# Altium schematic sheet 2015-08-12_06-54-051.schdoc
size 557 x 193 mm; SheetNumber: 1; SheetTotal: 1
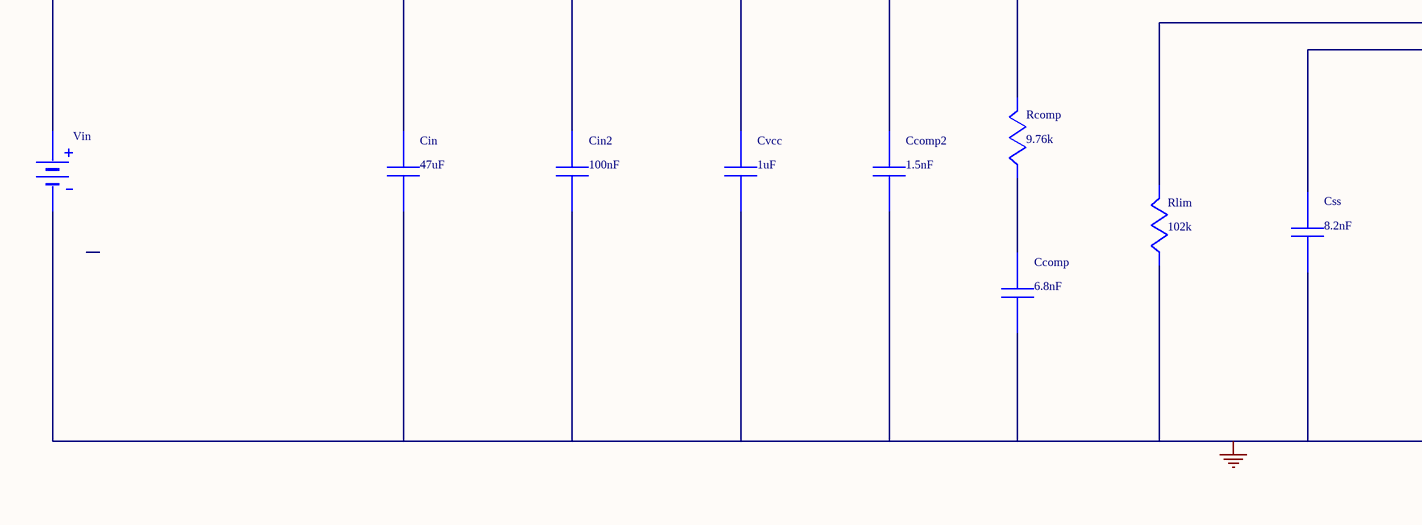
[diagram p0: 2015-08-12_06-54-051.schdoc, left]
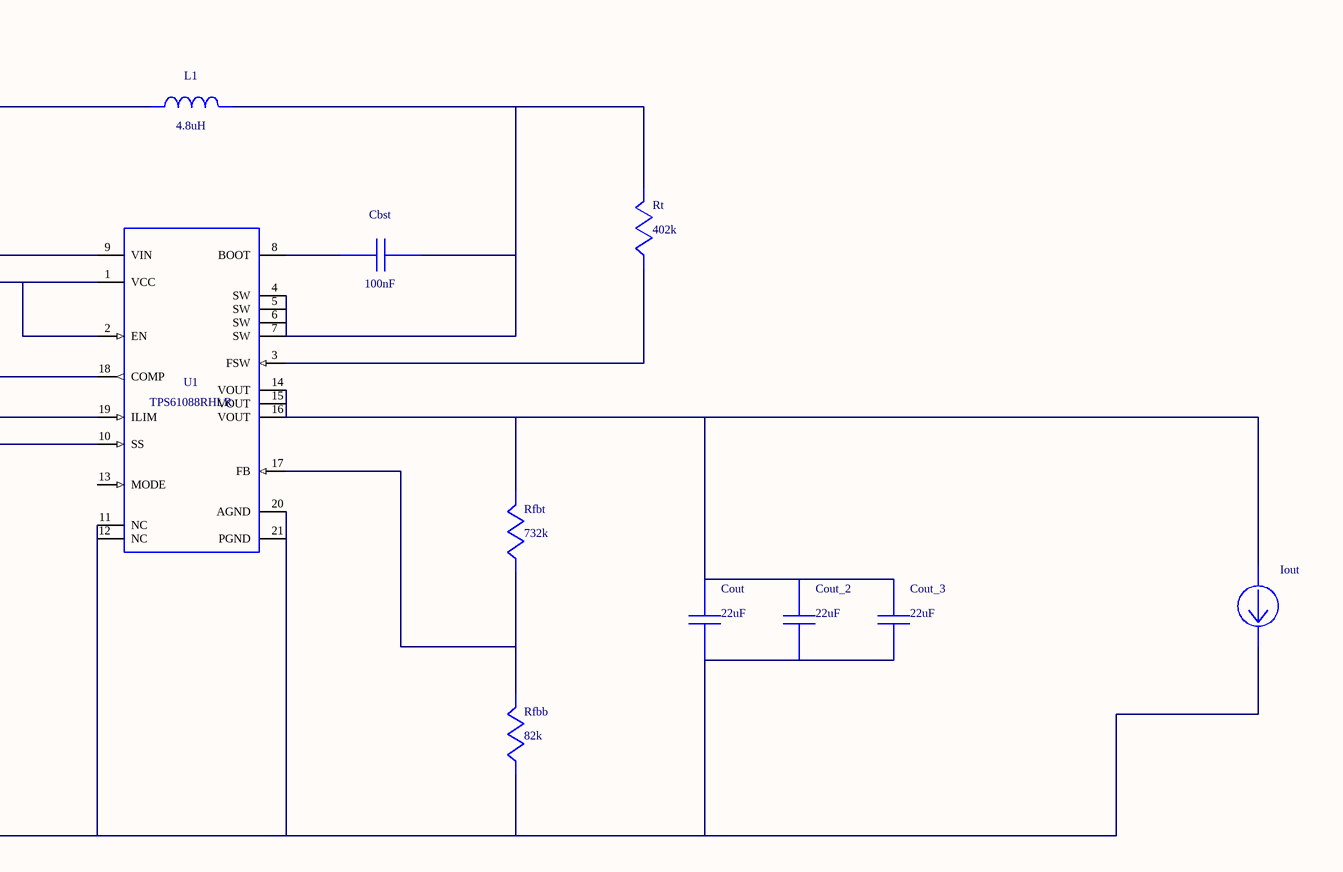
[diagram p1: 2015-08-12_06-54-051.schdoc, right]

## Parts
Cbst  value 100nF  (hidden comment: 08053C104KAT2A)
Ccomp  value 6.8nF  (hidden comment: CC0805KRX7R9BB682)
Ccomp2  value 1.5nF  (hidden comment: CC0805KRX7R9BB152)
Cin  value 47uF  (hidden comment: GRM32ER61A476KE20L)
Cin2  value 100nF  (hidden comment: GRM155R61A104KA01D)
Cout  value 22uF  (hidden comment: GRM32ER61E226KE15L)
Cout_2  value 22uF  (hidden comment: GRM32ER61E226KE15L)
Cout_3  value 22uF  (hidden comment: GRM32ER61E226KE15L)
Css  value 8.2nF  (hidden comment: GRM155R71C822KA01D)
Cvcc  value 1uF  (hidden comment: C1608X5R1A105K)
Iout  WB_CURRENT_LOAD  (value not drawn)
L1  value 4.8uH  (hidden comment: ETQPAF4R8HFA)
Rcomp  value 9.76k  (hidden comment: ERJ-6ENF9761V)
Rfbb  value 82k  (hidden comment: RR1220P-823-D)
Rfbt  value 732k  (hidden comment: CRCW0402732KFKED)
Rlim  value 102k  (hidden comment: ERJ-8ENF1023V)
Rt  value 402k  (hidden comment: ERJ-8ENF4023V)
U1  TPS61088RHLR
Vin  WB_BATTERY  (value not drawn)

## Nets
0: Ccomp.2 Ccomp2.2 Cin.2 Cin2.2 Cout.2 Cout_2.2 Cout_3.2 Css.2 Cvcc.2 Iout.2(-) Rfbb.2 Rlim.2 U1.11(NC) U1.12(NC) U1.20(AGND) U1.21(PGND) Vin.2(-)
NetCbst_1: Cbst.1 U1.8(BOOT)
NetCbst_2: Cbst.2 L1.2 Rt.1 U1.4(SW) U1.5(SW) U1.6(SW) U1.7(SW)
NetCcomp2_1: Ccomp2.1 Rcomp.1 U1.18(COMP)
NetCcomp_1: Ccomp.1 Rcomp.2
NetCin_1: Cin.1 Cin2.1 L1.1 U1.9(VIN) Vin.1(+)
NetCout_1: Cout.1 Cout_2.1 Cout_3.1 Iout.1(+) Rfbt.1 U1.14(VOUT) U1.15(VOUT) U1.16(VOUT)
NetCss_1: Css.1 U1.10(SS)
NetCvcc_1: Cvcc.1 U1.1(VCC) U1.2(EN)
NetRfbb_1: Rfbb.1 Rfbt.2 U1.17(FB)
NetRlim_1: Rlim.1 U1.19(ILIM)
NetRt_2: Rt.2 U1.3(FSW)

Not connected (* = marked no-connect by the designer): U1 13(MODE)

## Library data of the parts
Cbst = 08053C104KAT2A: Manufacturer Name: AVX
Ccomp = CC0805KRX7R9BB682: CC0805KRX7R9BB68; Manufacturer Name: Yageo America
Ccomp2 = CC0805KRX7R9BB152: CC0805KRX7R9BB15; Manufacturer Name: Yageo America
Cin = GRM32ER61A476KE20L: GRM32ER61A476KE2; Manufacturer Name: MuRata
Cin2 = GRM155R61A104KA01D: GRM155R61A104KA0; Manufacturer Name: MuRata
Cout Cout_2 Cout_3 = GRM32ER61E226KE15L: GRM32ER61E226KE1; Manufacturer Name: MuRata
Css = GRM155R71C822KA01D: GRM155R71C822KA0; Manufacturer Name: MuRata
Cvcc = C1608X5R1A105K: Manufacturer Name: TDK
Iout = WB_CURRENT_LOAD: Value: UNLISTED
L1 = ETQPAF4R8HFA: Manufacturer Name: Panasonic
Rcomp = ERJ-6ENF9761V: Manufacturer Name: Panasonic
Rfbb = RR1220P-823-D: Manufacturer Name: Susumu Co Ltd
Rfbt = CRCW0402732KFKED: Manufacturer Name: Vishay-Dale
Rlim = ERJ-8ENF1023V: Manufacturer Name: Panasonic
Rt = ERJ-8ENF4023V: Manufacturer Name: Panasonic
U1 = TPS61088RHLR: Manufacturer Name: Texas Instruments; Value: UNLISTED
Vin = WB_BATTERY: Value: UNLISTED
